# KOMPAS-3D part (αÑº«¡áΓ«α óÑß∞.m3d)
File: created 06.04.2016 12:01:11, last saved 23.07.2016 08:56:18.
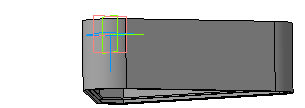
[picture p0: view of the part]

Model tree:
1. Эскиз:1
2. Операция выдавливания:1
     Толщина стенки 1 = 2; Толщина стенки 2 = 6; Расстояние 1 = 1
3. Эскиз:2
4. Операция выдавливания:2
     Толщина стенки 1 = 2; Толщина стенки 2 = 7; Расстояние 1 = 5
5. Эскиз:3
6. Операция выдавливания:3
     Толщина стенки 1 = 2; Толщина стенки 2 = 6; Расстояние 1 = 2
7. Эскиз:4
8. Операция выдавливания:4
     Толщина стенки 1 = 2; Толщина стенки 2 = 2.5; Расстояние 1 = 60
9. Эскиз:5
10. Вырезать элемент выдавливания:1
     Толщина стенки 2 = 1.5; Расстояние 1 = 40
11. Эскиз:6
12. Операция выдавливания:5
     Толщина стенки 1 = 2; Толщина стенки 2 = 2.5; Расстояние 1 = 20
13. Эскиз:7
14. Операция выдавливания:6
     Толщина стенки 1 = 2; Толщина стенки 2 = 6; Расстояние 1 = 2
15. Эскиз:8
16. Операция выдавливания:7
     Толщина стенки 1 = 2; Толщина стенки 2 = 6; Расстояние 1 = 5
17. Эскиз:9
18. Операция выдавливания:8
     Толщина стенки 1 = 2; Толщина стенки 2 = 6; Расстояние 1 = 1
19. Эскиз:10
20. Вырезать элемент выдавливания:2
     Толщина стенки 2 = 1.5; Расстояние 1 = 22
21. Эскиз:11
22. Вырезать элемент выдавливания:3
     Толщина стенки 2 = 1.5; Расстояние 1 = 1
23. Скругление:4
     Радиус = 1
